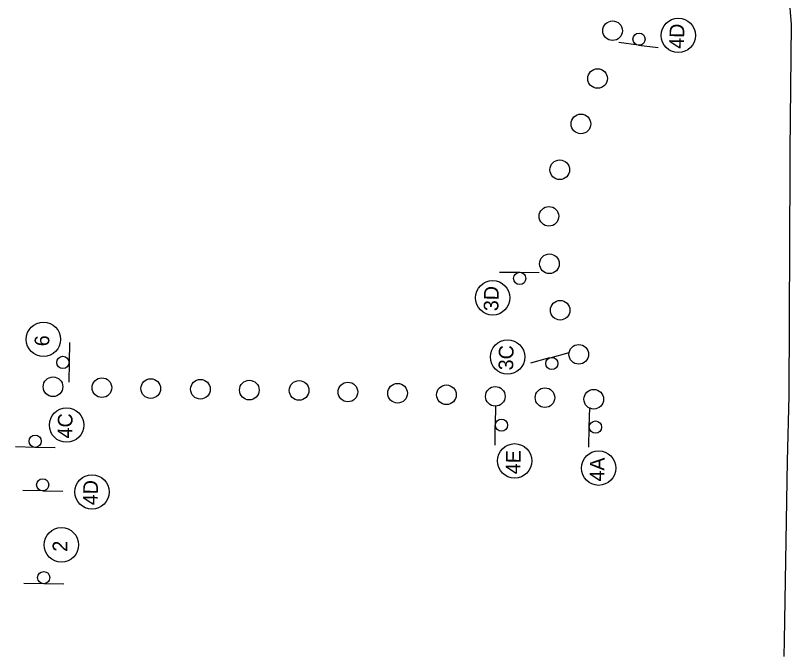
# Model space of a CAD drawing. Extents: x 345549 to 379569, y 127949 to 230467.
# Drawn here: x 355926 to 363865, y 182816 to 189370 of the extents above; entities that cross this region are included whole.
import ezdxf

# ---------------------------------------------------------------- set-up
doc = ezdxf.new("R2010")
doc.units = 0
for name, color, linetype in [('CA-TEXT', 7, 'Continuous'), ('CE-TOPO-CONC-SLAB', 7, 'Continuous'), ('Level 58', 7, 'Continuous'), ('SIGNS-POLES', 7, 'Continuous')]:
    doc.layers.add(name, color=color, linetype=linetype)

msp = doc.modelspace()

# ---------------------------------------------------------------- linework, layer by layer
at = {"layer": 'CA-TEXT'}
for centre in [(362706.9, 189166.4), (360808.2, 186483.4), (356212.4, 186058.7), (360959.9, 185878.4), (356448.8, 185181.7), (361032.8, 184816.3), (361891.7, 184741.7), (356708.6, 184498.7), (356396.5, 183957.4)]:
    msp.add_circle(centre, 175.9, dxfattribs=at)
at = {"layer": 'CE-TOPO-CONC-SLAB'}
for centre in [(362034.4, 189215), (361881.3, 188726.2), (361710.6, 188261.7), (361494.1, 187793.2), (361383.5, 187317.2), (361388.6, 186831.7), (361498.4, 186356.6), (361688.8, 185905.4), (356310.3, 185574), (356810.2, 185564.8), (357310.2, 185555.5), (357818.3, 185549), (358318.2, 185539.7), (358827.4, 185536.4), (359327.2, 185520.6), (359835.2, 185507.4), (360334.9, 185491.6), (360834.7, 185475.8), (361342.7, 185462.6), (361842.4, 185446.8)]:
    msp.add_circle(centre, 100.4, dxfattribs=at)
at = {"layer": 'Level 58'}
for points in [[(363852.8, 187986.2), (363864.7, 189279.9), (363842.4, 189573.8)], [(363842.2, 185480), (363851.2, 187817.5), (363852.8, 187986.2)], [(363794.1, 182980.3), (363823.5, 184811.4), (363842.2, 185480)], [(363790, 182815.8), (363794.1, 182980.3)]]:
    msp.add_lwpolyline(points, dxfattribs=at)
at = {"layer": 'SIGNS-POLES'}
for p, q in [((362298.9, 189067), (362098.3, 189094.6)), ((362501, 189039.2), (362300.2, 189065.3)), ((360878.8, 186747.3), (361081.3, 186746.2)), ((361082.8, 186744.7), (361285.2, 186742.1)), ((356478.3, 186027.9), (356475.8, 185825.3)), ((361395, 185871.3), (361590.4, 185924.3)), ((361198.1, 185817.9), (361393.2, 185872.4)), ((356474.2, 185823.9), (356470.2, 185621.4)), ((360836.1, 185180.3), (360840.2, 185382.8)), ((361796.6, 185161), (361800.6, 185363.4)), ((360832, 184976.3), (360834.6, 185178.8)), ((361792.4, 184957), (361795, 185159.5)), ((356128.9, 184954.4), (355926.5, 184958.4)), ((356332.9, 184950.2), (356130.4, 184952.8)), ((356205.4, 184508.5), (356003, 184512.6)), ((356409.4, 184504.4), (356206.9, 184507)), ((356215.6, 183559.6), (356013.1, 183563.6)), ((356419.5, 183555.4), (356217, 183558))]:
    msp.add_line(p, q, dxfattribs=at)
for centre in [(362305.1, 189129), (361084.3, 186682.4), (356411.9, 185822.8), (361413.5, 185811.8), (360898.4, 185181.4), (361858.8, 185162), (356127.9, 185016.6), (356204.4, 184570.8), (356214.5, 183621.8)]:
    msp.add_circle(centre, 62.6, dxfattribs=at)

# ---------------------------------------------------------------- texts
at = {"layer": 'CA-TEXT'}
for s, p in [('4D', (362764.1, 189029.2)), ('3D', (360865.4, 186346.2)), ('6', (356271, 185987)), ('3C', (361017.1, 185741.2)), ('4C', (356506, 185044.6)), ('4E', (361090, 184679.2)), ('4A', (361948.9, 184604.5)), ('4D', (356765.8, 184361.5)), ('2', (356455, 183885.7))]:
    msp.add_text(s, height=150, rotation=88.84682, dxfattribs=at).set_placement(p)

doc.saveas('drawing.dxf')
